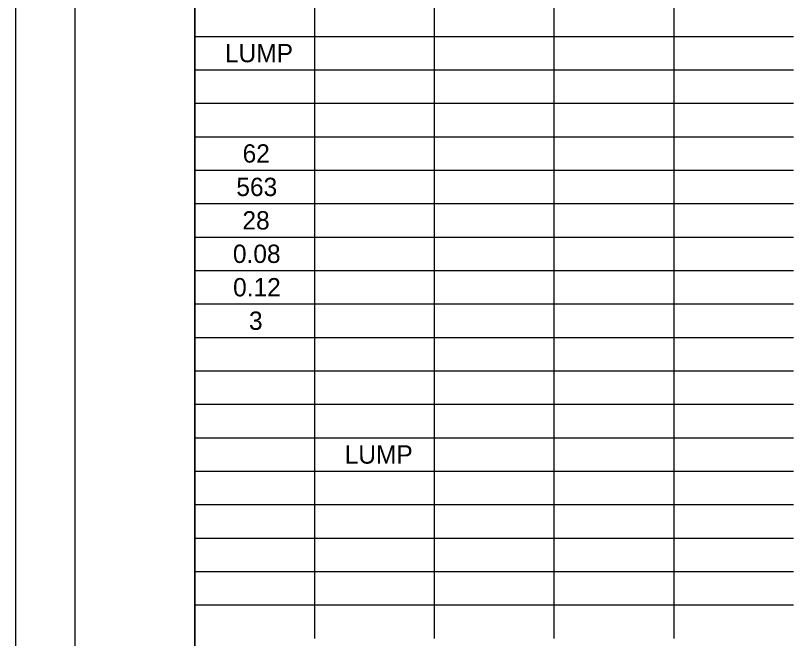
# Model space of a CAD drawing. Extents: x 0 to 34, y 0 to 22.
# Drawn here: x 0 to 6.51, y 11.42 to 16.63 of the extents above; entities that cross this region are included whole.
import ezdxf

# ---------------------------------------------------------------- set-up
doc = ezdxf.new("R2010")
doc.units = 0
for name, color, linetype in [('SH_Border', 7, 'Continuous'), ('SH_Cut_Line', 7, 'Continuous'), ('SH_Text', 7, 'Continuous')]:
    doc.layers.add(name, color=color, linetype=linetype)

msp = doc.modelspace()

# ---------------------------------------------------------------- linework, layer by layer
at = {"layer": 'SH_Border'}
for points in [[(0.5, 21.5), (1.5, 21.5), (1.5, 0.5), (0.5, 0.5)], [(1.5, 21.5), (33.5, 21.5), (33.5, 0.5), (1.5, 0.5)]]:
    msp.add_lwpolyline(points, close=True, dxfattribs=at)
at = {"layer": 'SH_Cut_Line'}
msp.add_lwpolyline([(0, 0), (34, 0), (34, 22), (0, 22)], close=True, dxfattribs=at)
at = {"layer": 'SH_Text'}
for p, q in [((1.5, 16.74), (1.5, 16.18)), ((2.5025, 16.74), (2.5025, 16.18)), ((3.5051, 16.74), (3.5051, 16.18)), ((4.5076, 16.74), (4.5076, 16.18)), ((5.5101, 16.74), (5.5101, 16.18)), ((1.5, 16.46), (6.5126, 16.46)), ((1.5, 16.18), (6.5126, 16.18)), ((1.5, 16.18), (1.5, 15.9)), ((2.5025, 16.18), (2.5025, 15.9)), ((3.5051, 16.18), (3.5051, 15.9)), ((4.5076, 16.18), (4.5076, 15.9)), ((5.5101, 16.18), (5.5101, 15.9)), ((1.5, 15.9), (6.5126, 15.9)), ((1.5, 15.9), (1.5, 15.62)), ((2.5025, 15.9), (2.5025, 15.62)), ((3.5051, 15.9), (3.5051, 15.62)), ((4.5076, 15.9), (4.5076, 15.62)), ((5.5101, 15.9), (5.5101, 15.62)), ((1.5, 15.62), (6.5126, 15.62)), ((1.5, 15.62), (1.5, 15.34)), ((2.5025, 15.62), (2.5025, 15.34)), ((3.5051, 15.62), (3.5051, 15.34)), ((4.5076, 15.62), (4.5076, 15.34)), ((5.5101, 15.62), (5.5101, 15.34)), ((1.5, 15.34), (6.5126, 15.34)), ((1.5, 15.34), (1.5, 14.78)), ((2.5025, 15.34), (2.5025, 14.78)), ((3.5051, 15.34), (3.5051, 14.78)), ((4.5076, 15.34), (4.5076, 14.78)), ((5.5101, 15.34), (5.5101, 14.78)), ((1.5, 15.06), (6.5126, 15.06)), ((1.5, 14.78), (6.5126, 14.78)), ((1.5, 14.78), (1.5, 14.5)), ((2.5025, 14.78), (2.5025, 14.5)), ((3.5051, 14.78), (3.5051, 14.5)), ((4.5076, 14.78), (4.5076, 14.5)), ((5.5101, 14.78), (5.5101, 14.5)), ((1.5, 14.5), (6.5126, 14.5)), ((1.5, 14.5), (1.5, 14.22)), ((2.5025, 14.5), (2.5025, 14.22)), ((3.5051, 14.5), (3.5051, 14.22)), ((4.5076, 14.5), (4.5076, 14.22)), ((5.5101, 14.5), (5.5101, 14.22)), ((1.5, 14.22), (6.5126, 14.22)), ((1.5, 14.22), (1.5, 13.94)), ((2.5025, 14.22), (2.5025, 13.94)), ((3.5051, 14.22), (3.5051, 13.94)), ((4.5076, 14.22), (4.5076, 13.94)), ((5.5101, 14.22), (5.5101, 13.94)), ((1.5, 13.94), (6.5126, 13.94)), ((1.5, 13.94), (1.5, 11.7)), ((2.5025, 13.94), (2.5025, 11.7)), ((3.5051, 13.94), (3.5051, 11.7)), ((4.5076, 13.94), (4.5076, 11.7)), ((5.5101, 13.94), (5.5101, 11.7)), ((1.5, 13.66), (6.5126, 13.66)), ((1.5, 13.38), (6.5126, 13.38)), ((1.5, 13.1), (6.5126, 13.1)), ((1.5, 12.82), (6.5126, 12.82)), ((1.5, 12.54), (6.5126, 12.54)), ((1.5, 12.26), (6.5126, 12.26)), ((1.5, 11.98), (6.5126, 11.98)), ((1.5, 11.7), (6.5126, 11.7)), ((1.5, 11.7), (1.5, 11.42)), ((2.5025, 11.7), (2.5025, 11.42)), ((3.5051, 11.7), (3.5051, 11.42)), ((4.5076, 11.7), (4.5076, 11.42)), ((5.5101, 11.7), (5.5101, 11.42))]:
    msp.add_line(p, q, dxfattribs=at)

# ---------------------------------------------------------------- texts
for s, height, p in [('LUMP', 0.15333, (1.7531, 16.2433)), ('62', 0.15333, (1.9009, 15.4033)), ('563', 0.15333, (1.8484, 15.1233)), ('28', 0.15333, (1.8994, 14.8433)), ('0.08', 0.15333, (1.8198, 14.5633)), ('0.12', 0.15333, (1.8213, 14.2833)), ('3', 0.1533, (1.9545, 14.0033)), ('LUMP', 0.15333, (2.7557, 12.8833))]:
    msp.add_text(s, height=height, dxfattribs=at).set_placement(p)

doc.saveas('drawing.dxf')
